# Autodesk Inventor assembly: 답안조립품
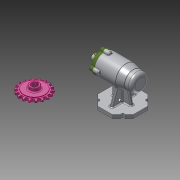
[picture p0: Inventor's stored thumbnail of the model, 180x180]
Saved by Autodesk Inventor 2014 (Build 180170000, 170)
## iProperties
Created: 2021-01
Part Number: 답안조립품
Document SubType Name: Assembly
Designer: kh
Author: kh
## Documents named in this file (12)
- C:\Users\kh\Desktop\710106V1011\답안조립품.iam
- C:\Users\kh\Desktop\710106V1011\본체.ipt
- C:\Users\kh\Desktop\710106V1011\멈춤나사 M3.ipt
- C:\Users\kh\Desktop\710106V1011\베어링 6004.ipt
- C:\Users\kh\Desktop\710106V1011\베어링 51202.ipt
- C:\Users\kh\Desktop\710106V1011\볼트 M4.ipt
- C:\Users\kh\Desktop\710106V1011\스프로킷.ipt
- C:\Users\kh\Desktop\710106V1011\어댑터슬리브.ipt
- C:\Users\kh\Desktop\710106V1011\오일 실.ipt
- C:\Users\kh\Desktop\710106V1011\축.ipt
- C:\Users\kh\Desktop\710106V1011\커버.ipt
- C:\Users\kh\Desktop\710106V1011\키 5 x 5 x 14.ipt
